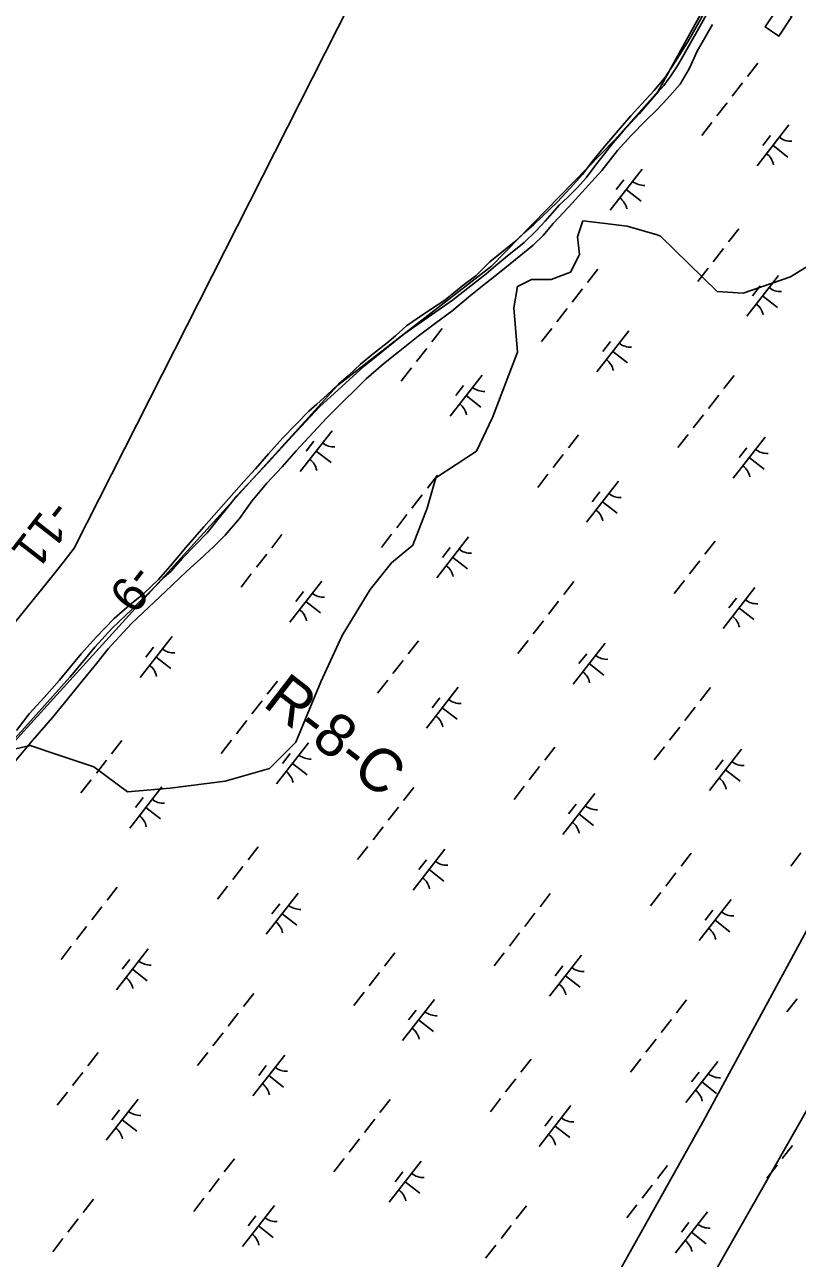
# Model space of a CAD drawing. Extents: x 3888273 to 3909528, y 158682 to 181032.
# Drawn here: x 3902718 to 3903461, y 170718 to 171905 of the extents above; entities that cross this region are included whole.
import ezdxf

# ---------------------------------------------------------------- set-up
doc = ezdxf.new("R2010")
doc.units = 0
for name, color, linetype in [('V-CHAN-DOCK', 7, 'Continuous'), ('V-RIVR-EDGE', 7, 'Continuous'), ('V-RIVR-JETY', 7, 'Continuous'), ('V-RIVR-RANG', 7, 'Continuous'), ('V-RIVR-RANG-IDEN', 7, 'Continuous'), ('V-RRAP-FSHR', 7, 'Continuous'), ('V-TOPO-DPTH', 7, 'Continuous'), ('V-TOPO-MINR', 7, 'Continuous'), ('V-UTIL-LINE', 7, 'Continuous'), ('V-WETL-SWMP', 7, 'Continuous')]:
    doc.layers.add(name, color=color, linetype=linetype)

msp = doc.modelspace()

# ---------------------------------------------------------------- linework, layer by layer
at = {"layer": 'V-CHAN-DOCK'}
msp.add_lwpolyline([(3903442.7, 171921.3), (3903430.2, 171902.5), (3903443.4, 171893.7), (3903455.9, 171912.5)], close=True, dxfattribs=at)
at = {"layer": 'V-RIVR-EDGE'}
for points in [[(3903678, 171923.3), (3903676.4, 171896.7), (3903665.5, 171868.6), (3903628, 171857.6), (3903581.1, 171854.5), (3903573.3, 171827.9), (3903582.6, 171815.4), (3903576.4, 171779.5), (3903581.1, 171740.4), (3903567, 171713.8), (3903545.1, 171704.4), (3903523.2, 171709.1), (3903474.8, 171674.7), (3903454.5, 171662.2), (3903409.1, 171646.6), (3903384.1, 171648.2), (3903329.4, 171701.3), (3903326.3, 171702.5)], [(3903326.3, 171702.5), (3903297.5, 171710.9), (3903268.5, 171714.3), (3903254.8, 171716), (3903249.7, 171700.7), (3903251.4, 171683.6), (3903242.9, 171666.6), (3903224.1, 171659.7), (3903205.4, 171659.7), (3903191.8, 171652.9), (3903188.3, 171632.5), (3903191.8, 171589.8), (3903167.9, 171526.8), (3903152.5, 171494.4), (3903113.3, 171468.8), (3903104.8, 171439.8), (3903091.2, 171404), (3903070.7, 171387), (3903050.2, 171361.4), (3903023, 171317.1), (3903002.5, 171272.7), (3902978.6, 171214.8), (3902953.1, 171189.2), (3902910.4, 171177.3), (3902857.6, 171170.4), (3902816.7, 171167), (3902784.3, 171190.9), (3902748.5, 171202.8), (3902722.9, 171211.4), (3902700.7, 171206.2)]]:
    msp.add_lwpolyline(points, dxfattribs=at)
at = {"layer": 'V-RIVR-JETY'}
for points in [[(3903387.5, 171939.4), (3903367.2, 171903), (3903349.7, 171871.8), (3903345, 171864.2), (3903339.5, 171855.4), (3903332.8, 171846.2), (3903327.3, 171840.1), (3903317.1, 171828.5), (3903308.9, 171818.9), (3903301, 171810.4), (3903293.5, 171802.4), (3903283.7, 171790.8), (3903275.5, 171780.3), (3903267.2, 171769.9), (3903257.8, 171757.5), (3903249.6, 171748.2), (3903240.1, 171738.6), (3903232.2, 171731.4), (3903225.2, 171723.3), (3903218.5, 171715.7), (3903209.4, 171706.1), (3903198.4, 171695.2), (3903180.3, 171680.7), (3903170.8, 171672.7), (3903161.8, 171665), (3903129.4, 171639.6), (3903082.4, 171606.9), (3903044.2, 171576.3), (3903001.2, 171537.3), (3902974.9, 171508.8), (3902952.1, 171483.9), (3902921.8, 171451.7), (3902893.2, 171416), (3902869.6, 171391.5), (3902858.2, 171378.7), (3902851.5, 171373.1), (3902843.6, 171364.6), (3902820.8, 171342.1), (3902801.9, 171324.4), (3902785, 171305.9), (3902765.3, 171281.9), (3902761, 171277.1), (3902755.5, 171271), (3902717.8, 171228.9), (3902693.8, 171202.8)], [(3903096.4, 171605.1), (3903112.9, 171617.6), (3903128.7, 171629.3), (3903146.5, 171644.2), (3903161.1, 171655.9), (3903174.5, 171666.3), (3903206.8, 171692.5), (3903216.6, 171701.8), (3903226.1, 171713.4), (3903241, 171729.1), (3903272.9, 171764.4), (3903288.2, 171783.7), (3903301.1, 171798.1), (3903315.3, 171812.6), (3903325.5, 171822.6), (3903335.8, 171833.5), (3903348.3, 171847.5), (3903357.3, 171862.7), (3903364.7, 171879.1), (3903372.1, 171891.9), (3903379.5, 171904.7)], [(3902707, 171194.6), (3902725, 171216.2), (3902744.3, 171238.3), (3902758.8, 171256), (3902771, 171271.2), (3902787.1, 171290.5), (3902798.1, 171304.5), (3902808.7, 171316.1), (3902820.9, 171329), (3902853.2, 171359.5), (3902873.3, 171378.8), (3902886.7, 171390.9), (3902899.3, 171402.6), (3902910.7, 171413.8), (3902924.4, 171429.9), (3902936.2, 171446.3), (3902950.7, 171463.6), (3902965.3, 171479.6), (3902979, 171494.9), (3902991.2, 171508.1), (3903008.5, 171526.6), (3903021.9, 171539.9), (3903038.4, 171556.3), (3903046.3, 171564), (3903062.8, 171578.5), (3903077, 171589.8), (3903096.4, 171605.1)]]:
    msp.add_lwpolyline(points, dxfattribs=at)
at = {"layer": 'V-RRAP-FSHR'}
msp.add_lwpolyline([(3902466.4, 170877.4), (3902596.5, 171071.9), (3902658.3, 171152.9), (3902704.7, 171211.9), (3903018.7, 171557.6), (3903166.9, 171672.4), (3903285.6, 171793.8), (3903327.1, 171840.6), (3903602.2, 172338.5), (3903762.1, 172628.9), (3903775.9, 172650.6), (3904124.4, 172985.1), (3904135.8, 173004.7), (3904140.8, 173195.6), (3904143.9, 173228.6), (3904155.6, 173256.3), (3904478.6, 173695.6), (3904503.4, 173735), (3904568.4, 173920.2), (3904627.6, 174008.5), (3904693.9, 174118.3), (3904723.9, 174185.4), (3904740.7, 174228.4), (3904769.8, 174251)], dxfattribs=at)
at = {"layer": 'V-TOPO-DPTH'}
msp.add_lwpolyline([(3903139.4, 172139.9), (3902765.2, 171401.2), (3902755.6, 171388.8), (3902745.9, 171376.6), (3902701.4, 171321.5)], dxfattribs=at)
at = {"layer": 'V-TOPO-MINR'}
msp.add_lwpolyline([(3902701.4, 171321.5), (3902745.9, 171376.6), (3902755.6, 171388.8), (3902765.2, 171401.2), (3903139.4, 172139.9)], dxfattribs=at)
at = {"layer": 'V-UTIL-LINE'}
for points in [[(3905528.7, 173697.1), (3904376.9, 172459.2), (3904350.4, 172426.1), (3904072.4, 171916.4), (3903483.3, 170883.7), (3902993.4, 170023.2), (3902953.7, 169950.4), (3902854.4, 169652.5), (3902708.8, 169268.5)], [(3902927.2, 169209), (3902847.8, 169559.8), (3902827.9, 169778.2), (3902907.4, 170023.2), (3903370.7, 170850.6), (3904006.2, 172022.3), (3904694.7, 172743.8), (3905561.8, 173664)]]:
    msp.add_lwpolyline(points, dxfattribs=at)
at = {"layer": 'V-WETL-SWMP'}
for p, q in [((3903364.9, 171904.6), (3903372.2, 171917.2)), ((3903355.7, 171888.1), (3903364.9, 171904.6)), ((3903345.3, 171871.5), (3903355.7, 171888.1)), ((3903334.1, 171854.5), (3903345.3, 171871.5)), ((3903423.1, 171867.5), (3903413.3, 171854.9)), ((3903323.3, 171841.5), (3903334.1, 171854.5)), ((3903408.4, 171848.6), (3903398.5, 171836)), ((3903311.6, 171828.4), (3903323.3, 171841.5)), ((3903300.8, 171817), (3903311.6, 171828.4)), ((3903393.6, 171829.6), (3903383.8, 171817)), ((3903291.1, 171805.5), (3903300.8, 171817)), ((3903276, 171787.7), (3903291.1, 171805.5)), ((3903378.9, 171810.7), (3903369.1, 171798.1)), ((3903453, 171808.2), (3903422.3, 171768.8)), ((3903435.3, 171798), (3903427.9, 171788.5)), ((3903437.7, 171788.5), (3903451.9, 171777.4)), ((3903264, 171773.5), (3903276, 171787.7)), ((3903254.4, 171760.5), (3903264, 171773.5)), ((3903311.8, 171765.8), (3903281.1, 171726.3)), ((3903242.4, 171747.4), (3903254.4, 171760.5)), ((3903294, 171755.5), (3903286.7, 171746)), ((3903230.4, 171734.4), (3903242.4, 171747.4)), ((3903296.4, 171746), (3903310.7, 171735)), ((3903207.5, 171712.6), (3903230.4, 171734.4)), ((3903197.8, 171704.3), (3903207.5, 171712.6)), ((3903404.7, 171708.3), (3903394.9, 171695.7)), ((3903165.2, 171676.5), (3903188.5, 171695.6)), ((3903188.5, 171695.6), (3903197.8, 171704.3)), ((3903390, 171689.4), (3903380.2, 171676.7)), ((3903151.6, 171663), (3903165.2, 171676.5)), ((3903269, 171669.5), (3903259.2, 171656.8)), ((3903375.2, 171670.4), (3903365.4, 171657.8)), ((3903139.2, 171653.9), (3903151.6, 171663)), ((3903443.1, 171663.6), (3903412.4, 171624.2)), ((3903120.9, 171639.2), (3903130.6, 171646.8)), ((3903130.6, 171646.8), (3903139.2, 171653.9)), ((3903254.3, 171650.5), (3903244.4, 171637.9)), ((3903425.3, 171653.4), (3903418, 171643.9)), ((3903108.1, 171630.9), (3903120.9, 171639.2)), ((3903427.7, 171643.9), (3903441.9, 171632.8)), ((3903085.1, 171615), (3903097.2, 171623.3)), ((3903097.2, 171623.3), (3903108.1, 171630.9)), ((3903239.5, 171631.6), (3903229.7, 171618.9)), ((3903074.3, 171605.4), (3903085.1, 171615)), ((3903119.3, 171612.4), (3903109.5, 171599.8)), ((3903224.8, 171612.6), (3903215, 171600)), ((3903298.9, 171610.2), (3903268.2, 171570.7)), ((3903053.3, 171588.4), (3903066.5, 171598.7)), ((3903066.5, 171598.7), (3903074.3, 171605.4)), ((3903281.2, 171599.9), (3903273.8, 171590.4)), ((3903040.9, 171578.1), (3903053.3, 171588.4)), ((3903104.6, 171593.4), (3903094.8, 171580.8)), ((3903283.6, 171590.4), (3903297.8, 171579.4)), ((3903029.2, 171567.4), (3903040.9, 171578.1)), ((3903089.9, 171574.5), (3903080, 171561.9)), ((3903019.5, 171559), (3903029.2, 171567.4)), ((3903157.7, 171567.7), (3903127, 171528.2)), ((3903400.3, 171567.3), (3903390.5, 171554.7)), ((3903008.7, 171548.7), (3903019.5, 171559)), ((3903139.9, 171557.5), (3903132.6, 171548)), ((3902991.2, 171532.9), (3902998.6, 171539.6)), ((3902998.6, 171539.6), (3903008.7, 171548.7)), ((3903142.3, 171548), (3903156.5, 171536.9)), ((3903385.5, 171548.4), (3903375.7, 171535.7)), ((3902966, 171507.2), (3902991.2, 171532.9)), ((3903370.8, 171529.4), (3903361, 171516.8)), ((3902952.1, 171492.1), (3902966, 171507.2)), ((3903013.5, 171514.2), (3902982.8, 171474.8)), ((3902995.8, 171504), (3902988.4, 171494.5)), ((3903250.6, 171510.2), (3903240.8, 171497.6)), ((3903356.1, 171510.5), (3903346.2, 171497.9)), ((3903430.2, 171508), (3903399.5, 171468.6)), ((3902939.7, 171477.5), (3902952.1, 171492.1)), ((3902998.2, 171494.5), (3903012.4, 171483.5)), ((3903235.9, 171491.3), (3903226, 171478.7)), ((3903412.5, 171497.8), (3903405.1, 171488.3)), ((3903414.9, 171488.3), (3903429.1, 171477.2)), ((3902928.5, 171465.3), (3902939.7, 171477.5)), ((3903114.9, 171471.4), (3903105.1, 171458.8)), ((3903221.1, 171472.4), (3903211.3, 171459.7)), ((3902890.1, 171421.8), (3902928.5, 171465.3)), ((3903289, 171465.6), (3903258.3, 171426.1)), ((3903100.2, 171452.5), (3903090.3, 171439.8)), ((3903271.2, 171455.3), (3903263.8, 171445.8)), ((3903273.6, 171445.8), (3903287.8, 171434.8)), ((3903085.4, 171433.5), (3903075.6, 171420.9)), ((3902872.7, 171402), (3902890.1, 171421.8)), ((3902965.2, 171414.3), (3902955.4, 171401.7)), ((3903070.7, 171414.6), (3903060.9, 171401.9)), ((3903144.8, 171412.1), (3903114.1, 171372.6)), ((3902857.6, 171383.8), (3902872.7, 171402)), ((3903127.1, 171401.8), (3903119.7, 171392.4)), ((3903381.9, 171408.1), (3903372.1, 171395.5)), ((3902950.5, 171395.4), (3902940.7, 171382.8)), ((3903129.5, 171392.4), (3903143.7, 171381.3)), ((3903367.2, 171389.2), (3903357.3, 171376.5)), ((3902846.4, 171371.2), (3902857.6, 171383.8)), ((3902935.7, 171376.4), (3902925.9, 171363.8)), ((3902832.1, 171357.3), (3902846.4, 171371.2)), ((3903003.6, 171369.6), (3902972.9, 171330.2)), ((3903246.2, 171369.3), (3903236.4, 171356.6)), ((3903352.4, 171370.2), (3903342.6, 171357.6)), ((3903420.3, 171363.4), (3903389.6, 171324)), ((3902818.9, 171346.6), (3902832.1, 171357.3)), ((3902985.8, 171359.4), (3902978.5, 171349.9)), ((3902988.2, 171349.9), (3903002.4, 171338.9)), ((3903231.4, 171350.3), (3903221.6, 171337.7)), ((3903402.5, 171353.2), (3903395.1, 171343.7)), ((3902803.7, 171333.5), (3902818.9, 171346.6)), ((3903404.9, 171343.7), (3903419.1, 171332.6)), ((3902786.3, 171315.7), (3902803.7, 171333.5)), ((3903216.7, 171331.4), (3903206.9, 171318.7)), ((3902772, 171299.5), (3902786.3, 171315.7)), ((3902859.4, 171316.2), (3902828.7, 171276.7)), ((3902841.7, 171305.9), (3902834.3, 171296.4)), ((3903096.5, 171312.2), (3903086.7, 171299.6)), ((3903202, 171312.4), (3903192.1, 171299.8)), ((3903276.1, 171310), (3903245.4, 171270.5)), ((3902761.5, 171286.9), (3902772, 171299.5)), ((3902844.1, 171296.4), (3902858.3, 171285.4)), ((3903081.8, 171293.2), (3903071.9, 171280.6)), ((3903258.4, 171299.7), (3903251, 171290.2)), ((3903260.8, 171290.2), (3903275, 171279.2)), ((3902751.1, 171274.2), (3902761.5, 171286.9)), ((3902736.4, 171257.6), (3902751.1, 171274.2)), ((3902960.8, 171273.3), (3902951, 171260.7)), ((3903067, 171274.3), (3903057.2, 171261.7)), ((3903134.9, 171267.5), (3903104.2, 171228)), ((3903377.5, 171267.1), (3903367.6, 171254.5)), ((3902722, 171241.8), (3902736.4, 171257.6)), ((3902946.1, 171254.4), (3902936.2, 171241.8)), ((3903117.1, 171257.2), (3903109.7, 171247.8)), ((3903119.5, 171247.8), (3903133.7, 171236.7)), ((3903362.7, 171248.2), (3903352.9, 171235.5)), ((3902709.7, 171226), (3902722, 171241.8)), ((3902931.3, 171235.4), (3902921.5, 171222.8)), ((3903348, 171229.2), (3903338.2, 171216.6)), ((3902811.1, 171216.3), (3902801.3, 171203.6)), ((3902916.6, 171216.5), (3902906.8, 171203.9)), ((3902990.7, 171214), (3902960, 171174.6)), ((3903227.8, 171210), (3903218, 171197.4)), ((3903333.2, 171210.3), (3903323.4, 171197.7)), ((3903407.4, 171207.8), (3903376.7, 171168.3)), ((3902796.4, 171197.3), (3902786.6, 171184.7)), ((3902973, 171203.8), (3902965.6, 171194.3)), ((3903389.6, 171197.6), (3903382.3, 171188.1)), ((3902975.4, 171194.3), (3902989.6, 171183.2)), ((3903213, 171191.1), (3903203.2, 171178.5)), ((3903392, 171188.1), (3903406.2, 171177)), ((3902781.6, 171178.4), (3902771.8, 171165.8)), ((3902849.5, 171171.6), (3902818.8, 171132.1)), ((3903092.1, 171171.2), (3903082.2, 171158.6)), ((3903198.3, 171172.2), (3903188.5, 171159.5)), ((3902831.7, 171161.3), (3902824.4, 171151.9)), ((3903266.1, 171165.4), (3903235.4, 171125.9)), ((3902834.1, 171151.9), (3902848.3, 171140.8)), ((3903077.3, 171152.2), (3903067.5, 171139.6)), ((3903248.4, 171155.1), (3903241, 171145.6)), ((3903250.8, 171145.6), (3903265, 171134.6)), ((3903062.6, 171133.3), (3903052.8, 171120.7)), ((3902942.4, 171114.1), (3902932.6, 171101.5)), ((3903047.9, 171114.4), (3903038, 171101.7)), ((3903122, 171111.9), (3903091.3, 171072.4)), ((3903104.2, 171101.6), (3903096.9, 171092.2)), ((3903359.1, 171107.9), (3903349.2, 171095.3)), ((3903464.5, 171108.1), (3903454.7, 171095.5)), ((3902927.7, 171095.2), (3902917.8, 171082.6)), ((3903106.7, 171092.2), (3903120.9, 171081.1)), ((3903344.3, 171089), (3903334.5, 171076.3)), ((3902912.9, 171076.2), (3902903.1, 171063.6)), ((3902806.7, 171075.3), (3902796.9, 171062.6)), ((3902980.8, 171069.4), (3902950.1, 171030)), ((3903223.4, 171069), (3903213.5, 171056.4)), ((3903329.6, 171070), (3903319.8, 171057.4)), ((3902791.9, 171056.3), (3902782.1, 171043.7)), ((3902963, 171059.2), (3902955.6, 171049.7)), ((3903397.4, 171063.2), (3903366.7, 171023.8)), ((3903379.7, 171053), (3903372.3, 171043.5)), ((3902965.4, 171049.7), (3902979.6, 171038.7)), ((3903208.6, 171050.1), (3903198.8, 171037.5)), ((3903382.1, 171043.5), (3903396.3, 171032.4)), ((3902777.2, 171037.4), (3902767.4, 171024.8)), ((3903193.9, 171031.2), (3903184.1, 171018.5)), ((3902762.5, 171018.4), (3902752.6, 171005.8)), ((3902836.6, 171016), (3902805.9, 170976.5)), ((3902818.9, 171005.7), (3902811.5, 170996.2)), ((3903073.7, 171012), (3903063.9, 170999.3)), ((3903179.1, 171012.2), (3903169.3, 170999.6)), ((3903253.3, 171009.7), (3903222.6, 170970.3)), ((3902821.3, 170996.2), (3902835.5, 170985.2)), ((3903058.9, 170993), (3903049.1, 170980.4)), ((3903235.5, 170999.5), (3903228.2, 170990)), ((3903237.9, 170990), (3903252.1, 170979)), ((3902938, 170973.1), (3902928.1, 170960.5)), ((3903044.2, 170974.1), (3903034.4, 170961.5)), ((3903112, 170967.3), (3903081.3, 170927.8)), ((3903354.6, 170966.9), (3903344.8, 170954.3)), ((3903460.9, 170967.9), (3903451, 170955.2)), ((3902923.2, 170954.2), (3902913.4, 170941.6)), ((3903094.3, 170957), (3903086.9, 170947.6)), ((3903096.7, 170947.6), (3903110.9, 170936.5)), ((3903339.9, 170948), (3903330.1, 170935.3)), ((3902908.5, 170935.2), (3902898.7, 170922.6)), ((3903325.2, 170929), (3903315.3, 170916.4)), ((3902788.3, 170916.1), (3902778.5, 170903.4)), ((3902893.8, 170916.3), (3902883.9, 170903.7)), ((3902967.9, 170913.8), (3902937.2, 170874.4)), ((3903310.4, 170910.1), (3903300.6, 170897.4)), ((3902950.1, 170903.6), (3902942.8, 170894.1)), ((3903205, 170909.8), (3903195.1, 170897.2)), ((3903384.6, 170907.6), (3903353.9, 170868.1)), ((3902773.6, 170897.1), (3902763.7, 170884.5)), ((3902952.5, 170894.1), (3902966.8, 170883)), ((3903190.2, 170890.9), (3903180.4, 170878.3)), ((3903366.8, 170897.3), (3903359.4, 170887.9)), ((3903369.2, 170887.9), (3903383.4, 170876.8)), ((3902758.8, 170878.2), (3902749, 170865.5)), ((3902826.7, 170871.4), (3902796, 170831.9)), ((3903069.2, 170871), (3903059.4, 170858.4)), ((3903175.5, 170871.9), (3903165.7, 170859.3)), ((3903243.3, 170865.2), (3903212.6, 170825.7)), ((3902808.9, 170861.1), (3902801.5, 170851.6)), ((3902811.3, 170851.6), (3902825.5, 170840.6)), ((3903054.5, 170852), (3903044.7, 170839.4)), ((3903225.6, 170854.9), (3903218.2, 170845.4)), ((3903228, 170845.4), (3903242.2, 170834.4)), ((3903039.8, 170833.1), (3903029.9, 170820.5)), ((3903456.4, 170826.9), (3903446.6, 170814.2)), ((3902919.6, 170813.9), (3902909.7, 170801.3)), ((3903025, 170814.2), (3903015.2, 170801.5)), ((3903099.2, 170811.7), (3903068.5, 170772.2)), ((3903336.2, 170807.7), (3903326.4, 170795.1)), ((3903441.7, 170807.9), (3903431.9, 170795.3)), ((3902904.8, 170795), (3902895, 170782.3)), ((3903081.4, 170801.4), (3903074.1, 170792)), ((3903083.8, 170791.9), (3903098, 170780.9)), ((3903321.5, 170788.7), (3903311.7, 170776.1)), ((3902783.9, 170775.1), (3902774, 170762.4)), ((3902890.1, 170776), (3902880.3, 170763.4)), ((3902957.9, 170769.2), (3902927.2, 170729.8)), ((3903200.5, 170768.8), (3903190.7, 170756.2)), ((3903306.8, 170769.8), (3903296.9, 170757.2)), ((3902769.1, 170756.1), (3902759.3, 170743.5)), ((3902940.2, 170759), (3902932.8, 170749.5)), ((3903374.6, 170763), (3903343.9, 170723.5)), ((3902942.6, 170749.5), (3902956.8, 170738.4)), ((3903185.8, 170749.9), (3903176, 170737.3)), ((3903356.8, 170752.7), (3903349.5, 170743.3)), ((3902754.4, 170737.2), (3902744.6, 170724.5)), ((3903359.3, 170743.3), (3903373.5, 170732.2)), ((3903171.1, 170731), (3903161.2, 170718.3))]:
    msp.add_line(p, q, dxfattribs=at)
for centre, start, end in [((3903454.8, 171810.1), 231.343, 272.8866), ((3903420.9, 171766.5), 11.343, 52.8866), ((3903313.6, 171767.7), 231.343, 272.8866), ((3903279.7, 171724.1), 11.343, 52.8866), ((3903444.9, 171665.6), 231.343, 272.8866), ((3903411, 171622), 11.343, 52.8866), ((3903300.7, 171612.1), 231.343, 272.8866), ((3903266.8, 171568.5), 11.343, 52.8866), ((3903159.5, 171569.6), 231.343, 272.8866), ((3903125.6, 171526), 11.343, 52.8866), ((3903015.3, 171516.2), 231.343, 272.8866), ((3903432, 171509.9), 231.343, 272.8866), ((3902981.4, 171472.6), 11.343, 52.8866), ((3903398.1, 171466.3), 11.343, 52.8866), ((3903290.8, 171467.5), 231.343, 272.8866), ((3903256.8, 171423.9), 11.343, 52.8866), ((3903146.6, 171414), 231.343, 272.8866), ((3903112.7, 171370.4), 11.343, 52.8866), ((3903005.4, 171371.6), 231.343, 272.8866), ((3903422.1, 171365.3), 231.343, 272.8866), ((3902971.5, 171328), 11.343, 52.8866), ((3903388.1, 171321.7), 11.343, 52.8866), ((3902861.2, 171318.1), 231.343, 272.8866), ((3903277.9, 171311.9), 231.343, 272.8866), ((3902827.3, 171274.5), 11.343, 52.8866), ((3903244, 171268.3), 11.343, 52.8866), ((3903136.7, 171269.4), 231.343, 272.8866), ((3903102.7, 171225.8), 11.343, 52.8866), ((3902992.5, 171216), 231.343, 272.8866), ((3903409.2, 171209.7), 231.343, 272.8866), ((3902958.6, 171172.4), 11.343, 52.8866), ((3903375.3, 171166.1), 11.343, 52.8866), ((3902851.3, 171173.5), 231.343, 272.8866), ((3903267.9, 171167.3), 231.343, 272.8866), ((3902817.4, 171129.9), 11.343, 52.8866), ((3903234, 171123.7), 11.343, 52.8866), ((3903123.8, 171113.8), 231.343, 272.8866), ((3903089.9, 171070.2), 11.343, 52.8866), ((3902982.6, 171071.4), 231.343, 272.8866), ((3902948.6, 171027.8), 11.343, 52.8866), ((3903399.2, 171065.1), 231.343, 272.8866), ((3903365.3, 171021.5), 11.343, 52.8866), ((3902838.4, 171017.9), 231.343, 272.8866), ((3903255.1, 171011.7), 231.343, 272.8866), ((3902804.5, 170974.3), 11.343, 52.8866), ((3903221.2, 170968.1), 11.343, 52.8866), ((3903113.8, 170969.2), 231.343, 272.8866), ((3903079.9, 170925.6), 11.343, 52.8866), ((3902969.7, 170915.7), 231.343, 272.8866), ((3902935.8, 170872.1), 11.343, 52.8866), ((3903386.4, 170909.5), 231.343, 272.8866), ((3903352.4, 170865.9), 11.343, 52.8866), ((3902828.5, 170873.3), 231.343, 272.8866), ((3903245.1, 170867.1), 231.343, 272.8866), ((3902794.5, 170829.7), 11.343, 52.8866), ((3903211.2, 170823.5), 11.343, 52.8866), ((3903101, 170813.6), 231.343, 272.8866), ((3903067.1, 170770), 11.343, 52.8866), ((3902959.7, 170771.2), 231.343, 272.8866), ((3903376.4, 170764.9), 231.343, 272.8866), ((3902925.8, 170727.6), 11.343, 52.8866), ((3903342.5, 170721.3), 11.343, 52.8866)]:
    msp.add_arc(centre, 17.6, start, end, dxfattribs=at)

# ---------------------------------------------------------------- texts
at = {"layer": 'V-RIVR-RANG'}
for s, p in [('-11', (3902743.1, 171450.3)), ('-9', (3902821.7, 171388.5))]:
    msp.add_text(s, height=33.5, rotation=232.1583, dxfattribs=at).set_placement(p)
at = {"layer": 'V-RIVR-RANG-IDEN'}
msp.add_text('R-8-C', height=41.5, rotation=322.3015, dxfattribs=at).set_placement((3902945.6, 171250.3))

doc.saveas('drawing.dxf')
